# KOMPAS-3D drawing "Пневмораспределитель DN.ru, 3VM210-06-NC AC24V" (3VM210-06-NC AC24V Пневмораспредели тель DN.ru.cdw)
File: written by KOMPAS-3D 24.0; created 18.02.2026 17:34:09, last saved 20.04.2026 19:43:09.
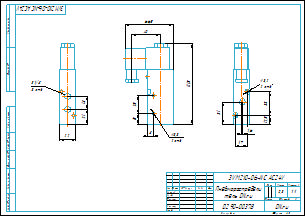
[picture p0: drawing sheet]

Document properties: Автор: R2D2; Форматы листов документа: A3; Полное имя файла: 3VM210-06-NC AC24V Пневмораспределитель DN.ru.m3d; Масса: 0.3; Наименование: Пневмораспределитель DN.ru; Количество листов документа: 1; Примечание: D290-00378

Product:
- Part/product: Пневмораспределитель DN.ru  | designation 3VM210-06-NC AC24V
    Масса: 0.3
    Раздел спецификации: Прочие изделия
    Форматы листов документа: A3
    Примечание: D290-00378

Views: Вид 1, Спереди, Проекционный вид 2, Проекционный вид 3
Referenced files in E:\Работа\Зайцев\Аксессуары для пневмоприводов\Пневмораспределители DN.ru\3VM210-06-NC Пневмораспределитель DN.RU\AC24V\: 3VM210-06-NC AC24V Пневмораспределитель DN.ru.m3d
Referenced files in E:\Работа\Зайцев\Для компаса\: чертеж DN.ru А3.cdt
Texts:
  Линейный размер
  чертеж DN.ru А3.cdt
  Пневмораспредели
  тель DN.ru
  Пневмораспределитель DN.ru
  3VM210-06-NC AC24V Пневмораспределитель DN.ru
Dimensions and other numbers on the sheet: 0; 3; 2; 4; 3 отв.; 21; 18; 22; 3VM210-06-NC AC24V; 66,5; 40; 111,5; 3,3; 2 отв.; 15; 25; 8; 3,2; 33; 12,5; 17; 1,6; 31; 1:1; 1; 0,3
